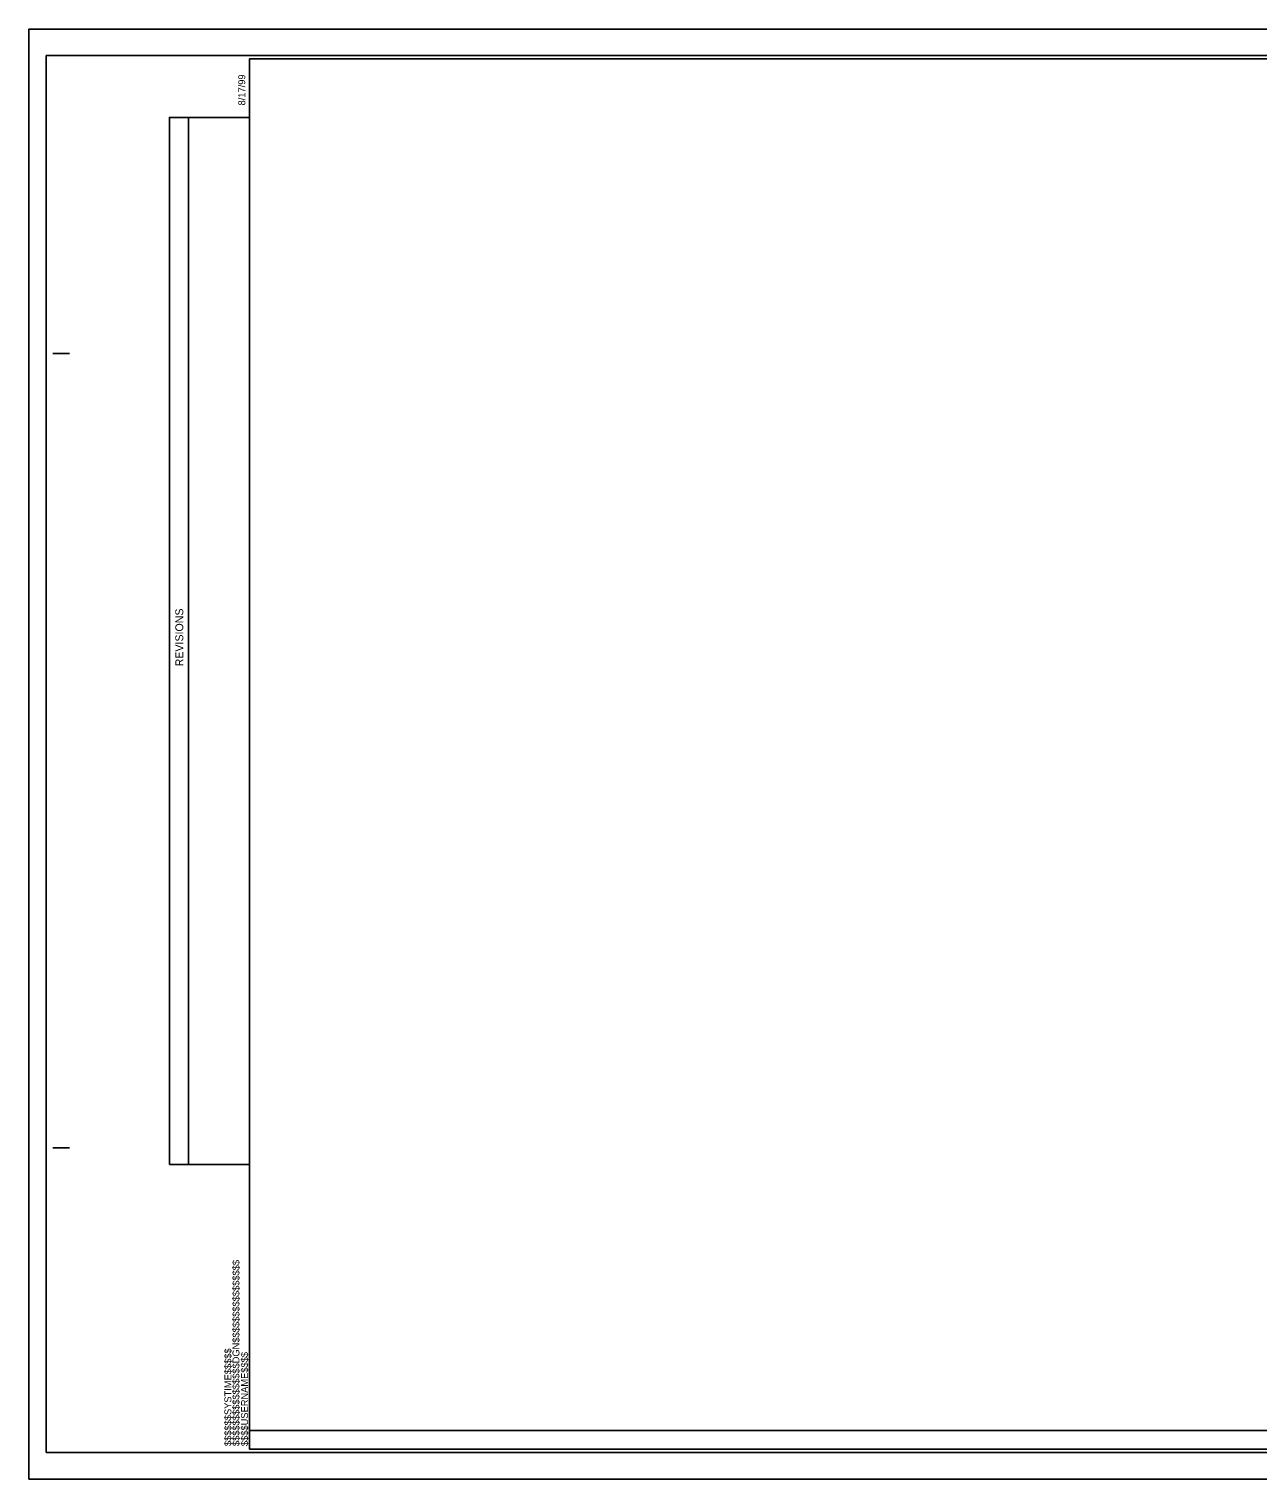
# Model space of a CAD drawing. Extents: x 2862872 to 2864765, y 971793 to 972888.
# Drawn here: x 2862872 to 2863800, y 971793 to 972888 of the extents above; entities that cross this region are included whole.
import ezdxf

# ---------------------------------------------------------------- set-up
doc = ezdxf.new("R2010")
doc.units = 0
for name, color, linetype in [('Sheet Block Revision CELL', 7, 'Continuous'), ('Sheet Cutting Line CELL', 7, 'Continuous'), ('Sheet Plan CELL', 7, 'Continuous'), ('Sheet Plot Border Inside CELL', 7, 'Continuous'), ('Sheet Plot Border Outside CELL', 7, 'Continuous'), ('Sheet XS Number', 7, 'Continuous')]:
    doc.layers.add(name, color=color, linetype=linetype)

msp = doc.modelspace()

# ---------------------------------------------------------------- linework, layer by layer
at = {"layer": 'Sheet Block Revision CELL'}
msp.add_line((2862992.6, 972030.8), (2862992.6, 972821.5), dxfattribs=at)
msp.add_line((2862992.6, 972030.8), (2862992.6, 972821.5), dxfattribs=at)
msp.add_lwpolyline([(2862978.1, 972030.8), (2862978.1, 972821.5), (2863038.6, 972821.5), (2863038.6, 972030.8)], close=True, dxfattribs=at)
msp.add_lwpolyline([(2862978.1, 972030.8), (2862978.1, 972821.5), (2863038.6, 972821.5), (2863038.6, 972030.8)], close=True, dxfattribs=at)
at = {"layer": 'Sheet Cutting Line CELL'}
for p, q in [((2864555.6, 972888.3), (2862872.1, 972888.3)), ((2862872.1, 972888.3), (2862872.1, 971793.3)), ((2862872.1, 971793.3), (2864555.6, 971793.3))]:
    msp.add_line(p, q, dxfattribs=at)
at = {"layer": 'Sheet Plan CELL'}
for p, q in [((2863038.6, 972865.8), (2863038.6, 972865.8)), ((2863038.6, 972865.8), (2863038.6, 972865.8)), ((2862890.1, 972643.3), (2862902.6, 972643.3)), ((2862890.1, 972643.3), (2862902.6, 972643.3)), ((2862890.1, 972043.3), (2862902.6, 972043.3)), ((2862890.1, 972043.3), (2862902.6, 972043.3)), ((2863038.6, 971815.8), (2863038.6, 971815.8)), ((2863038.6, 971815.8), (2863038.6, 971815.8))]:
    msp.add_line(p, q, dxfattribs=at)
msp.add_lwpolyline([(2864538.7, 972865.8), (2863038.6, 972865.8), (2863038.6, 971815.8), (2864538.6, 971815.8)], close=True, dxfattribs=at)
msp.add_lwpolyline([(2864538.7, 972865.8), (2863038.6, 972865.8), (2863038.6, 971815.8), (2864538.6, 971815.8)], close=True, dxfattribs=at)
at = {"layer": 'Sheet Plot Border Inside CELL'}
msp.add_lwpolyline([(2862885.1, 971813.3), (2864551.1, 971813.3), (2864551.1, 972868.3), (2862885.1, 972868.3)], close=True, dxfattribs=at)
at = {"layer": 'Sheet Plot Border Outside CELL'}
msp.add_lwpolyline([(2862872.1, 971793.3), (2864555.6, 971793.3), (2864555.6, 972888.3), (2862872.1, 972888.3)], close=True, dxfattribs=at)
msp.add_lwpolyline([(2862872.1, 971793.3), (2864555.6, 971793.3), (2864555.6, 972888.3), (2862872.1, 972888.3)], close=True, dxfattribs=at)
at = {"layer": 'Sheet XS Number'}
msp.add_lwpolyline([(2863038.6, 971830), (2864538.6, 971830), (2864538.6, 972865.8), (2863038.6, 972865.8)], close=True, dxfattribs=at)

# ---------------------------------------------------------------- texts
at = {"layer": 'Sheet Block Revision CELL'}
msp.add_text('REVISIONS', height=6, rotation=90, dxfattribs=at).set_placement((2862988.6, 972407))
msp.add_text('REVISIONS', height=6, rotation=90, dxfattribs=at).set_placement((2862988.6, 972407))
at = {"layer": 'Sheet Plan CELL'}
for s, p in [('8/17/99', (2863035.4, 972830.6)), ('8/17/99', (2863035.4, 972830.6)), ('$$$$$$$$$$$$$$$$DGN$$$$$$$$$$$$$$$$', (2863031, 971818.2)), ('$$$$$$$$$$$$$$$$DGN$$$$$$$$$$$$$$$$', (2863031, 971818.2)), ('$$$$$$SYSTIME$$$$$', (2863024.9, 971818.2)), ('$$$$$$SYSTIME$$$$$', (2863024.9, 971818.2)), ('$$$$USERNAME$$$$', (2863037.5, 971818.2)), ('$$$$USERNAME$$$$', (2863037.5, 971818.2))]:
    msp.add_text(s, height=5.25, rotation=90, dxfattribs=at).set_placement(p)

doc.saveas('drawing.dxf')
